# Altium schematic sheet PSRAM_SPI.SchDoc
size A4; Organization: HTL Hollabrunn; Address1: Abteilung Elektronik; Address2: Anton Ehrenfried-Straße 10; Address3: 2020 Hollabrunn; SPICEModelCacheKLVIFSCJ: <root> / <DocumentId>KLVIFSCJ</DocumentId> / <CacheFrame Number="0"> / <Model Name="cap" Kind="MDL"> / <Text>*Default semiconductor capacitor / .MODEL CAP C()</Text> / </Model> / </CacheFrame> / </root>
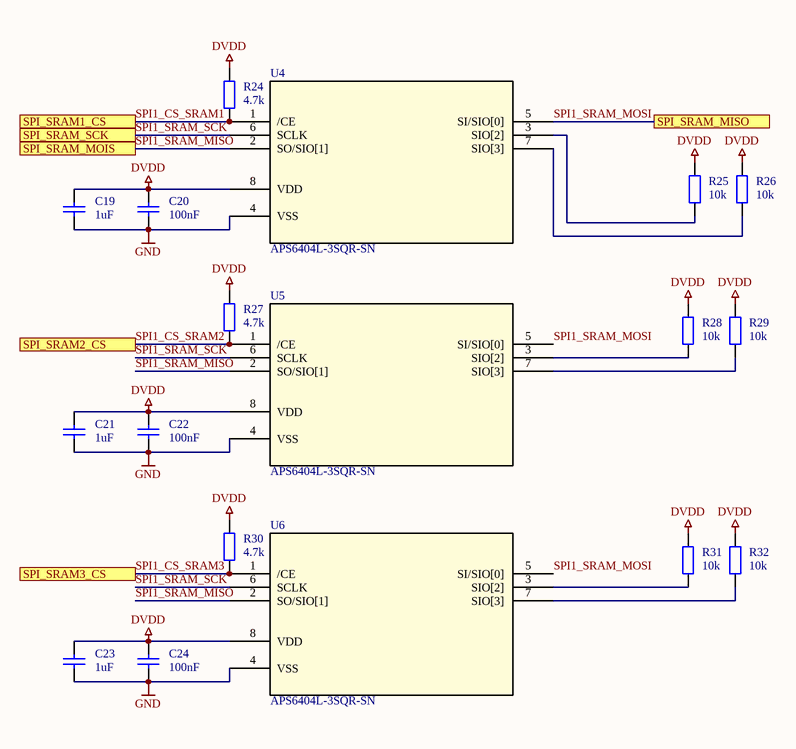
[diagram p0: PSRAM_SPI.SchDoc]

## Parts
C19  1uF  [C1206-KUE]
C20  100nF  [C1206-KUE]
C21  1uF  [C1206-KUE]
C22  100nF  [C1206-KUE]
C23  1uF  [C1206-KUE]
C24  100nF  [C1206-KUE]
R24  4.7k  [C1206-KUE]
R25  10k  [C1206-KUE]
R26  10k  [C1206-KUE]
R27  4.7k  [C1206-KUE]
R28  10k  [C1206-KUE]
R29  10k  [C1206-KUE]
R30  4.7k  [C1206-KUE]
R31  10k  [C1206-KUE]
R32  10k  [C1206-KUE]
U4  APS6404L-3SQR-SN  [APS6404L-3SQR-SN_APY]
U5  APS6404L-3SQR-SN  [APS6404L-3SQR-SN_APY]
U6  APS6404L-3SQR-SN  [APS6404L-3SQR-SN_APY]

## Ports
SPI_SRAM1_CS, SPI_SRAM2_CS, SPI_SRAM3_CS, SPI_SRAM_MISO, SPI_SRAM_MOIS, SPI_SRAM_SCK

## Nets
DVDD: C19.2 C20.2 C21.2 C22.2 C23.2 C24.2 R24.1 R25.1 R26.1 R27.1 R28.1 R29.1 R30.1 R31.1 R32.1 U4.8(VDD) U5.8(VDD) U6.8(VDD)
GND: C19.1 C20.1 C21.1 C22.1 C23.1 C24.1 U4.4(VSS) U5.4(VSS) U6.4(VSS)
SPI1_CS_SRAM1: R24.2 U4.1(/CE) ; port SPI_SRAM1_CS
SPI1_CS_SRAM2: R27.2 U5.1(/CE) ; port SPI_SRAM2_CS
SPI1_CS_SRAM3: R30.2 U6.1(/CE) ; port SPI_SRAM3_CS
SPI1_SRAM_MISO: U4.2(SO/SIO[1]) U5.2(SO/SIO[1]) U6.2(SO/SIO[1]) ; port SPI_SRAM_MOIS
SPI1_SRAM_MOSI: U4.5(SI/SIO[0]) U5.5(SI/SIO[0]) U6.5(SI/SIO[0]) ; port SPI_SRAM_MISO
SPI1_SRAM_SCK: U4.6(SCLK) U5.6(SCLK) U6.6(SCLK) ; port SPI_SRAM_SCK
NetR25_2: R25.2 U4.3(SIO[2])
NetR26_2: R26.2 U4.7(SIO[3])
NetR28_2: R28.2 U5.3(SIO[2])
NetR29_2: R29.2 U5.7(SIO[3])
NetR31_2: R31.2 U6.3(SIO[2])
NetR32_2: R32.2 U6.7(SIO[3])

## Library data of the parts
C19-C24 = Capacitor: Manufacturer: Kemet; Bezeichnung: Kerko +-10% 63V
R24-R32 = ResistorSMD: Resistor SMD; Manufacturer: AVX; Bezeichnung: SMD Wid. 1/8W 2%
U4-U6 = APS6404L-3SQR-SN: Description; Manufacturer_Name: AP Memory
